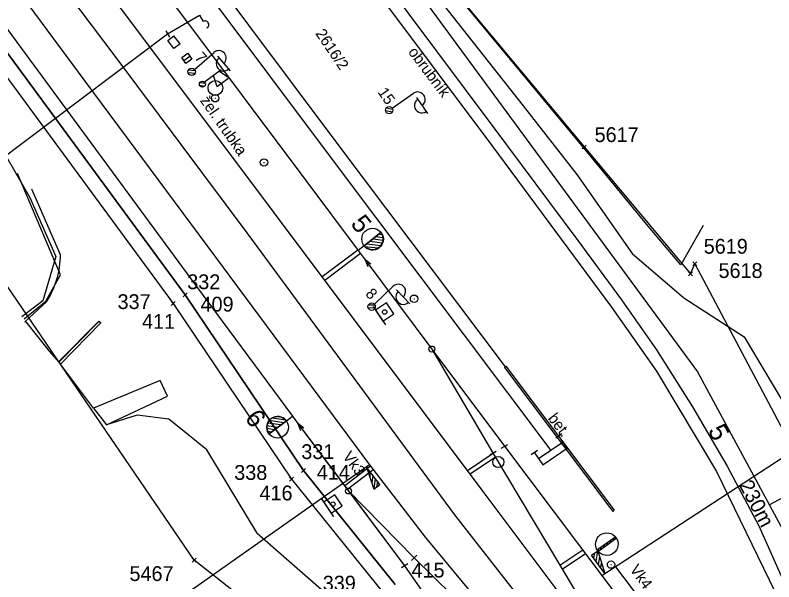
# Model space of a CAD drawing. Extents: x -804166 to -803706, y -1151030 to -1150147.
# Drawn here: x -804028.2 to -803925.7, y -1150394.5 to -1150318 of the extents above; entities that cross this region are included whole.
import ezdxf

# ---------------------------------------------------------------- set-up
doc = ezdxf.new("R2010")
doc.units = 0
for name, color, linetype in [('0381KM032-037P - Vrstva 1', 7, 'Continuous'), ('0381KM032-037P - Vrstva 13', 7, 'Continuous'), ('0381KM032-037P - Vrstva 15', 7, 'Continuous'), ('0381KM032-037P - Vrstva 16', 7, 'Continuous'), ('0381KM032-037P - Vrstva 17', 7, 'Continuous'), ('0381KM032-037P - Vrstva 2', 7, 'Continuous'), ('0381KM032-037P - Vrstva 25', 7, 'Continuous'), ('0381KM032-037P - Vrstva 27', 7, 'Continuous'), ('0381KM032-037P - Vrstva 3', 7, 'Continuous'), ('0381KM032-037P - Vrstva 33', 7, 'Continuous'), ('0381KM032-037P - Vrstva 4', 7, 'Continuous'), ('0381KM032-037P - Vrstva 41', 7, 'Continuous'), ('0381KM032-037P - Vrstva 43', 7, 'Continuous'), ('0381KM032-037P - Vrstva 48', 7, 'Continuous'), ('0381KM032-037P - Vrstva 49', 7, 'Continuous'), ('0381KM032-037P - Vrstva 50', 7, 'Continuous'), ('0381KM032-037P - Vrstva 51', 7, 'Continuous'), ('0381KM032-037P - Vrstva 57', 7, 'Continuous'), ('0381KM032-037P - Vrstva 7', 7, 'Continuous'), ('DZ_CD - CD', 7, 'Continuous'), ('DZ_CD - CD_krizek', 7, 'Continuous'), ('DZ_CD - CD_čísla', 7, 'Continuous'), ('szdc - hran DP', 7, 'Continuous'), ('szdc - szdc_cislo', 7, 'Continuous'), ('szdc - szdc_krizek', 7, 'Continuous'), ('VB - VB', 7, 'Continuous'), ('VB - VB_cislo', 7, 'Continuous'), ('VB - VB_krizek', 7, 'Continuous')]:
    doc.layers.add(name, color=color, linetype=linetype)

msp = doc.modelspace()

# ---------------------------------------------------------------- linework, layer by layer
at = {"layer": '0381KM032-037P - Vrstva 1'}
for points in [[(-804087.93, -1150205.28), (-804078.71, -1150215.28), (-804072.37, -1150222.52), (-804072.08, -1150222.85), (-804071.47, -1150223.58), (-804065.48, -1150230.82), (-804059.47, -1150238.51), (-804055.55, -1150243.68), (-804054.36, -1150245.27), (-804043.89, -1150259.22), (-804035.37, -1150270.61), (-804034.4, -1150271.93), (-804017.97, -1150293.92), (-804002.6, -1150314.46), (-803985.38, -1150337.43), (-803955.87, -1150376.72)], [(-804089.35, -1150206.44), (-804078.67, -1150220.7), (-804069.15, -1150233.38), (-804067.86, -1150235.11), (-804059.28, -1150246.53), (-804058.07, -1150248.16), (-804048.7, -1150260.65), (-804037.85, -1150275.13), (-804021.63, -1150296.76), (-804006.14, -1150317.34), (-803988.98, -1150340.29), (-803981.9, -1150349.73)], [(-804090.39, -1150214.38), (-804086.65, -1150219.55), (-804073.82, -1150237.11), (-804072.56, -1150238.83), (-804064.05, -1150250.31), (-804062.81, -1150251.97), (-804052.29, -1150266.05), (-804042.5, -1150279.11), (-804026.55, -1150300.33), (-804011.27, -1150320.63), (-803993.37, -1150344.49), (-803965.17, -1150382.07), (-803953.84, -1150397.19)], [(-804093.97, -1150217.42), (-804088.17, -1150225.67), (-804077.51, -1150240.28), (-804068.52, -1150252.21), (-804067.31, -1150253.81), (-804055.01, -1150270.12), (-804046.09, -1150281.93), (-804030.05, -1150303.21), (-804014.76, -1150323.52), (-803996.92, -1150347.35), (-803968.88, -1150385.42), (-803942.6, -1150419.03)], [(-804095.55, -1150218.38), (-804090.74, -1150227.08), (-804084.01, -1150238.21), (-804078.76, -1150245.78), (-804072.11, -1150254.85), (-804070.85, -1150256.55), (-804059.97, -1150271.29), (-804049.56, -1150285.37), (-804034.13, -1150306.22), (-804018.79, -1150326.86), (-804001.18, -1150350.63), (-803980.37, -1150378.68), (-803972.82, -1150388.42), (-803965.21, -1150397.6)], [(-804088.45, -1150239.45), (-804070.36, -1150264.07), (-804054.98, -1150285.05), (-804052.95, -1150287.79), (-804037.56, -1150308.64), (-804021.87, -1150329.91), (-804004.48, -1150353.56), (-803990.76, -1150372.09)], [(-804011.14, -1150262.39), (-804005.45, -1150273.41), (-803998.73, -1150284.85), (-803991.51, -1150295.63), (-803978.8, -1150312.77), (-803963.69, -1150332.99), (-803952.21, -1150348.36), (-803946.3, -1150356.39), (-803941.6, -1150363.14), (-803936.71, -1150370.83), (-803932.05, -1150378.84), (-803927.78, -1150386.91), (-803924.06, -1150395.18), (-803920.62, -1150403.65), (-803918.06, -1150410.86), (-803915.07, -1150420.32), (-803912.96, -1150427.25), (-803910.49, -1150435.34), (-803907.33, -1150445.05), (-803903.67, -1150454.38), (-803897.94, -1150464.6), (-803891.97, -1150476.6)], [(-803981.9, -1150349.73), (-803980.96, -1150350.97), (-803971.94, -1150363.03), (-803962.12, -1150376.15)], [(-803981.9, -1150349.73), (-803980.96, -1150350.97), (-803971.94, -1150363.03), (-803963.66, -1150377.12)], [(-803990.76, -1150372.09), (-803990.03, -1150373.08), (-803975.62, -1150392.3)], [(-803990.76, -1150372.09), (-803990.03, -1150373.08), (-803983.2, -1150382.19), (-803974.33, -1150391.21)], [(-803962.12, -1150376.15), (-803948.98, -1150393.6), (-803935.25, -1150411.89)], [(-803963.66, -1150377.12), (-803952.72, -1150395.46)], [(-803974.33, -1150391.21), (-803966.54, -1150398.86)], [(-803975.62, -1150392.3), (-803939.47, -1150444.12), (-803928.27, -1150459.42), (-803914.53, -1150477.73)]]:
    msp.add_lwpolyline(points, dxfattribs=at)
at = {"layer": '0381KM032-037P - Vrstva 13'}
for p, q in [((-804016.94, -1150359.26), (-804022.35, -1150364.74)), ((-804016.92, -1150359.32), (-804022.32, -1150364.8)), ((-804022.11, -1150365.08), (-804016.66, -1150359.51)), ((-804022.35, -1150364.74), (-804022.32, -1150364.8)), ((-804022.32, -1150364.8), (-804022.11, -1150365.08))]:
    msp.add_line(p, q, dxfattribs=at)
msp.add_lwpolyline([(-804016.66, -1150359.51), (-804016.92, -1150359.32), (-804016.94, -1150359.26), (-804016.66, -1150359.51)], dxfattribs=at)
at = {"layer": '0381KM032-037P - Vrstva 15'}
for p, q in [((-803954.37, -1150374.48), (-803955.2, -1150375.05)), ((-803954.22, -1150375.59), (-803957.52, -1150377.85)), ((-803957.67, -1150376.74), (-803958.5, -1150377.31))]:
    msp.add_line(p, q, dxfattribs=at)
msp.add_lwpolyline([(-803958.08, -1150377.03), (-803956.95, -1150378.68), (-803953.66, -1150376.41), (-803954.79, -1150374.76)], dxfattribs=at)
at = {"layer": '0381KM032-037P - Vrstva 16'}
for p, q in [((-803962.14, -1150365.5), (-803961.94, -1150365.35)), ((-803962.14, -1150365.5), (-803947.5, -1150384.94)), ((-803961.94, -1150365.35), (-803947.3, -1150384.79)), ((-803947.5, -1150384.94), (-803947.3, -1150384.79))]:
    msp.add_line(p, q, dxfattribs=at)
at = {"layer": '0381KM032-037P - Vrstva 17'}
for p, q in [((-803935.29, -1150346.34), (-803938.3, -1150351.66)), ((-804026.76, -1150359.35), (-804023.62, -1150363.33)), ((-804023.62, -1150363.33), (-804022.35, -1150364.74)), ((-804017.62, -1150371.01), (-804022.11, -1150365.08)), ((-804008.64, -1150367.29), (-804017.62, -1150371.01)), ((-804007.64, -1150369.41), (-804008.64, -1150367.29)), ((-804015.88, -1150373.24), (-804007.64, -1150369.41))]:
    msp.add_line(p, q, dxfattribs=at)
for points in [[(-803938.3, -1150351.66), (-803942.72, -1150346.43), (-803950.36, -1150337.11), (-803959.95, -1150325.57), (-803969.63, -1150313.89), (-803978.45, -1150303.11), (-803982.31, -1150298.44), (-803989.47, -1150289.34)], [(-804026.99, -1150358.95), (-804024.09, -1150356.55), (-804022.1, -1150353.01), (-804027.89, -1150339.34)], [(-804026.92, -1150359.34), (-804026.76, -1150359.35)], [(-804017.62, -1150371.01), (-804015.88, -1150373.24)]]:
    msp.add_lwpolyline(points, dxfattribs=at)
at = {"layer": '0381KM032-037P - Vrstva 2'}
for p, q in [((-803981.09, -1150349.09), (-803978.8, -1150347.27)), ((-803978.8, -1150347.27), (-803981.09, -1150349.09)), ((-803979.93, -1150348.17), (-803978.49, -1150348.33)), ((-803979.51, -1150347.84), (-803978.5, -1150347.96)), ((-803979.09, -1150347.51), (-803978.62, -1150347.56)), ((-803981.1, -1150349.09), (-803981.9, -1150349.73)), ((-803981.09, -1150349.09), (-803981.09, -1150349.09)), ((-803981.02, -1150349.17), (-803979.13, -1150349.39)), ((-803980.76, -1150348.82), (-803978.78, -1150349.06)), ((-803980.35, -1150348.49), (-803978.58, -1150348.7)), ((-803991.59, -1150372.71), (-803993.93, -1150374.46)), ((-803993.93, -1150374.46), (-803991.59, -1150372.71)), ((-803991.93, -1150372.97), (-803993.9, -1150372.68)), ((-803991.66, -1150372.63), (-803993.54, -1150372.35)), ((-803991.59, -1150372.71), (-803990.76, -1150372.09)), ((-803991.59, -1150372.71), (-803991.59, -1150372.71)), ((-803992.78, -1150373.6), (-803994.21, -1150373.39)), ((-803993.2, -1150373.92), (-803994.21, -1150373.77)), ((-803992.35, -1150373.28), (-803994.11, -1150373.03)), ((-803993.63, -1150374.24), (-803994.1, -1150374.17)), ((-803962.55, -1150376.41), (-803961.69, -1150375.9)), ((-803963.23, -1150376.87), (-803964.1, -1150377.37)), ((-803983.2, -1150382.19), (-803974.33, -1150391.21)), ((-803973.98, -1150390.86), (-803974.69, -1150391.56)), ((-803975.19, -1150392.03), (-803976.04, -1150392.56))]:
    msp.add_line(p, q, dxfattribs=at)
for points in [[(-803981.9, -1150349.73), (-803980.96, -1150350.97), (-803971.94, -1150363.03), (-803962.12, -1150376.15)], [(-803980.18, -1150351.59), (-803980.96, -1150350.97), (-803980.59, -1150351.9)], [(-803971.94, -1150363.03), (-803963.66, -1150377.12)], [(-803990.76, -1150372.09), (-803990.03, -1150373.08), (-803983.2, -1150382.19), (-803975.62, -1150392.3)], [(-803989.25, -1150373.71), (-803990.03, -1150373.08), (-803989.66, -1150374.02)]]:
    msp.add_lwpolyline(points, dxfattribs=at)
for centre, radius in [((-803979.94, -1150348.18), 1.46), ((-803971.94, -1150363.03), 0.4), ((-803992.77, -1150373.59), 1.46), ((-803983.2, -1150382.19), 0.4)]:
    msp.add_circle(centre, radius, dxfattribs=at)
for centre, start, end in [((-803979.95, -1150348.18), 218.2901, 38.251), ((-803992.76, -1150373.59), 36.7889, 216.7498)]:
    msp.add_arc(centre, 1.46, start, end, dxfattribs=at)
at = {"layer": '0381KM032-037P - Vrstva 25'}
for p, q in [((-804004.01, -1150325.29), (-804001.36, -1150322.99)), ((-804000.9, -1150323.52), (-803999.2, -1150325.49)), ((-804004.87, -1150325.72), (-804003.91, -1150325.79)), ((-804004.81, -1150325.35), (-804003.93, -1150325.41)), ((-803977.29, -1150330.5), (-803974.41, -1150328.51)), ((-803974.01, -1150329.08), (-803972.53, -1150331.22)), ((-803978.2, -1150330.83), (-803977.25, -1150331.01)), ((-803978.09, -1150330.47), (-803977.23, -1150330.63)), ((-803979.7, -1150356.96), (-803977.17, -1150354.55)), ((-803976.69, -1150355.05), (-803974.89, -1150356.93)), ((-803980.55, -1150357.43), (-803979.59, -1150357.46)), ((-803980.5, -1150357.06), (-803979.62, -1150357.08))]:
    msp.add_line(p, q, dxfattribs=at)
for centre in [(-804004.38, -1150325.62), (-804004.38, -1150325.62), (-803977.7, -1150330.78), (-803977.7, -1150330.78), (-803980.07, -1150357.31), (-803980.07, -1150357.31)]:
    msp.add_circle(centre, 0.5, dxfattribs=at)
for centre, start, end in [((-804000.71, -1150323.75), 310.9638, 130.9638), ((-804000.06, -1150324.51), 130.2612, 311.6663), ((-803973.84, -1150329.33), 304.6353, 124.6353), ((-803973.28, -1150330.16), 123.9327, 305.3379), ((-803976.48, -1150355.27), 313.6296, 133.6296), ((-803975.8, -1150356), 132.927, 314.3322)]:
    msp.add_arc(centre, 1, start, end, dxfattribs=at)
at = {"layer": '0381KM032-037P - Vrstva 27'}
for p, q in [((-803974.39, -1150356.24), (-803974.29, -1150356.24)), ((-803947.78, -1150392.13), (-803947.68, -1150392.13))]:
    msp.add_line(p, q, dxfattribs=at)
for centre in [(-803974.34, -1150356.24), (-803947.73, -1150392.13)]:
    msp.add_circle(centre, 0.5, dxfattribs=at)
at = {"layer": '0381KM032-037P - Vrstva 3'}
for p, q in [((-803994.66, -1150337.85), (-803994.56, -1150337.85)), ((-803979.88, -1150357.31), (-803978.21, -1150359.75)), ((-803978.08, -1150356.8), (-803979.54, -1150357.8)), ((-803977.08, -1150358.26), (-803978.08, -1150356.8)), ((-803979.54, -1150357.8), (-803978.54, -1150359.26)), ((-803978.54, -1150359.26), (-803977.08, -1150358.26)), ((-803948.98, -1150393.6), (-803893.86, -1150357.66)), ((-803980.37, -1150378.68), (-804019.01, -1150405.81)), ((-803980.57, -1150379.24), (-803980.6, -1150379.48)), ((-803980.25, -1150379.66), (-803980.33, -1150380.27)), ((-803979.93, -1150380.08), (-803980.06, -1150381.04)), ((-803979.61, -1150380.49), (-803979.79, -1150381.82)), ((-803979.29, -1150380.91), (-803979.4, -1150381.66)), ((-803978.98, -1150381.32), (-803978.99, -1150381.34)), ((-803986.86, -1150383.23), (-803985.21, -1150385.68)), ((-803985.06, -1150382.73), (-803986.53, -1150383.72)), ((-803984.07, -1150384.2), (-803985.06, -1150382.73)), ((-803986.53, -1150383.72), (-803985.54, -1150385.19)), ((-803985.54, -1150385.19), (-803984.07, -1150384.2)), ((-803948.26, -1150389.47), (-803948.21, -1150389.18)), ((-803947.82, -1150389.15), (-803947.78, -1150388.87)), ((-803947.39, -1150388.84), (-803947.34, -1150388.55)), ((-803947.1, -1150388.64), (-803947.1, -1150388.6)), ((-803949.74, -1150391.69), (-803949.51, -1150390.29)), ((-803949.14, -1150390.1), (-803949.08, -1150389.8)), ((-803948.7, -1150389.78), (-803948.65, -1150389.49)), ((-803950.05, -1150391.26), (-803949.94, -1150390.55)), ((-803949.43, -1150392.13), (-803949.25, -1150391.1)), ((-803949.12, -1150392.56), (-803949, -1150391.92)), ((-803948.8, -1150392.99), (-803948.75, -1150392.72))]:
    msp.add_line(p, q, dxfattribs=at)
for points in [[(-803980.77, -1150378.99), (-803979.76, -1150381.93), (-803978.97, -1150381.33), (-803980.77, -1150378.99)], [(-803947.08, -1150388.62), (-803947.2, -1150388.45), (-803949.5, -1150390.11), (-803949.38, -1150390.27), (-803947.08, -1150388.62)], [(-803948.58, -1150393.31), (-803950.35, -1150390.85), (-803949.52, -1150390.25), (-803948.58, -1150393.31)]]:
    msp.add_lwpolyline(points, dxfattribs=at)
msp.add_lwpolyline([(-803947.08, -1150388.62), (-803947.2, -1150388.45), (-803949.5, -1150390.11), (-803949.38, -1150390.27)], close=True, dxfattribs=at)
for centre, radius in [((-803994.61, -1150337.85), 0.5), ((-803978.31, -1150358.03), 0.296), ((-803985.3, -1150383.96), 0.296)]:
    msp.add_circle(centre, radius, dxfattribs=at)
msp.add_ellipse((-803948.29, -1150389.36), major_axis=(-1.23, -0.89), ratio=0.999996, dxfattribs=at)
at = {"layer": '0381KM032-037P - Vrstva 33'}
for p, q in [((-804000.39, -1150325.35), (-804002.63, -1150327.02)), ((-804000.63, -1150325.53), (-803999.33, -1150326.43)), ((-804000.93, -1150327.62), (-804001.43, -1150326.12)), ((-803999.33, -1150326.43), (-804000.93, -1150327.62)), ((-804003.3, -1150327.43), (-804002.63, -1150327.53)), ((-804003.25, -1150327.03), (-804002.56, -1150327.14))]:
    msp.add_line(p, q, dxfattribs=at)
msp.add_circle((-804002.93, -1150327.28), 0.401, dxfattribs=at)
msp.add_circle((-804002.93, -1150327.28), 0.401, dxfattribs=at)
at = {"layer": '0381KM032-037P - Vrstva 4'}
for points in [[(-804015.09, -1150257.7), (-804005.61, -1150276.65), (-803997.81, -1150289.61), (-803985.99, -1150305.97), (-803963.83, -1150335.54), (-803947.69, -1150357.39), (-803941.6, -1150366.02), (-803933.49, -1150379.54), (-803925.57, -1150395.83), (-803919.57, -1150411.36), (-803915.11, -1150425.7)], [(-804033.34, -1150270.47), (-804023.51, -1150283.74), (-804006.75, -1150306.05), (-804002.75, -1150311.23), (-803984.52, -1150335.59), (-803962.04, -1150365.45)]]:
    msp.add_lwpolyline(points, dxfattribs=at)
at = {"layer": '0381KM032-037P - Vrstva 41'}
for p, q in [((-804007.63, -1150320.5), (-804003.32, -1150317.97)), ((-804003.32, -1150317.97), (-804002.82, -1150318.83)), ((-804063.79, -1150362.63), (-804007.63, -1150320.5)), ((-804007.89, -1150320.07), (-804007.38, -1150320.93))]:
    msp.add_line(p, q, dxfattribs=at)
msp.add_arc((-804002.56, -1150319.25), 0.5, 299.3257, 121.6172, dxfattribs=at)
at = {"layer": '0381KM032-037P - Vrstva 43'}
msp.add_line((-804005.93, -1150321.83), (-804006.77, -1150320.75), dxfattribs=at)
for points in [[(-804005.93, -1150321.83), (-804006.79, -1150322.47), (-804007.61, -1150321.38), (-804006.77, -1150320.75)], [(-804005.45, -1150324.07), (-804005.73, -1150323.66), (-804004.91, -1150323.09), (-804004.34, -1150323.91), (-804005.16, -1150324.48), (-804005.45, -1150324.07), (-804004.63, -1150323.5)]]:
    msp.add_lwpolyline(points, dxfattribs=at)
msp.add_circle((-804001.17, -1150327.79), 1, dxfattribs=at)
at = {"layer": '0381KM032-037P - Vrstva 48'}
msp.add_line((-803918.27, -1150379.71), (-803926.34, -1150384.07), dxfattribs=at)
at = {"layer": '0381KM032-037P - Vrstva 49'}
for p, q in [((-804022.74, -1150350.54), (-804024.47, -1150356.54)), ((-804024.47, -1150356.54), (-804027.3, -1150358.69)), ((-803929.73, -1150361.39), (-803920.94, -1150376.21))]:
    msp.add_line(p, q, dxfattribs=at)
for points in [[(-804010.87, -1150255.86), (-804001.61, -1150274.67), (-803994.7, -1150286.68), (-803981.46, -1150304.36), (-803936.05, -1150366.09), (-803921.77, -1150392.54), (-803912.22, -1150419.28), (-803908.81, -1150430.91)], [(-804067.58, -1150273.2), (-804053.47, -1150291.61), (-804044.04, -1150305.1), (-804036.58, -1150319.92), (-804030.41, -1150335.37), (-804026.23, -1150342.57), (-804022.74, -1150350.54)], [(-803989.47, -1150289.34), (-803982.88, -1150300.61), (-803979.03, -1150305.25), (-803971.78, -1150314.79), (-803959.62, -1150330.2), (-803952.37, -1150339.47), (-803944.88, -1150350.15), (-803937.92, -1150356.12), (-803929.73, -1150361.39)], [(-803995.51, -1150387.87), (-804002.35, -1150376.64), (-804007.46, -1150372.51), (-804011.72, -1150371.94), (-804015.88, -1150373.24)], [(-803995.51, -1150387.87), (-803978.95, -1150402.37), (-803967.97, -1150412.01), (-803952.57, -1150434.32)]]:
    msp.add_lwpolyline(points, dxfattribs=at)
at = {"layer": '0381KM032-037P - Vrstva 50'}
msp.add_line((-804001.26, -1150329.18), (-804001.16, -1150329.18), dxfattribs=at)
msp.add_circle((-804001.21, -1150329.18), 0.5, dxfattribs=at)
at = {"layer": '0381KM032-037P - Vrstva 51'}
for p, q in [((-804022.1, -1150350.3), (-804025.97, -1150341.45)), ((-804026.92, -1150359.34), (-804023.98, -1150356.66)), ((-803947.12, -1150392.44), (-803936.56, -1150406.26))]:
    msp.add_line(p, q, dxfattribs=at)
msp.add_lwpolyline([(-804015.09, -1150257.7), (-804005.61, -1150276.65), (-803997.81, -1150289.61), (-803985.99, -1150305.97), (-803963.83, -1150335.54), (-803947.69, -1150357.39), (-803941.6, -1150366.02), (-803933.49, -1150379.54), (-803925.57, -1150395.83), (-803919.57, -1150411.36), (-803915.11, -1150425.7)], dxfattribs=at)
msp.add_ellipse((-804033.55, -1150350.88), major_axis=(7.51, 9.2), ratio=0.940819, start_param=4.845934, end_param=5.41758, dxfattribs=at)
at = {"layer": '0381KM032-037P - Vrstva 7'}
for p, q in [((-803981.94, -1150349.67), (-803986.77, -1150353.29)), ((-803981.58, -1150350.15), (-803986.41, -1150353.77)), ((-803963.66, -1150377.12), (-803967.14, -1150379.45)), ((-803963.35, -1150377.64), (-803966.78, -1150379.93)), ((-803980.24, -1150378.86), (-803983.71, -1150381.51)), ((-803979.87, -1150379.33), (-803983.35, -1150381.99)), ((-803951.56, -1150390.2), (-803954.63, -1150392.26)), ((-803951.2, -1150390.68), (-803954.32, -1150392.78))]:
    msp.add_line(p, q, dxfattribs=at)
msp.add_circle((-803962.96, -1150378.29), 0.75, dxfattribs=at)
at = {"layer": 'DZ_CD - CD'}
for p, q in [((-804042.88, -1150308), (-804006.89, -1150356.88)), ((-804005.25, -1150355.72), (-804040.67, -1150307.63)), ((-803989.28, -1150379.42), (-804005.25, -1150355.72)), ((-804006.89, -1150356.88), (-803990.89, -1150380.61)), ((-803976.88, -1150394.8), (-803989.28, -1150379.42)), ((-803990.89, -1150380.61), (-803978.48, -1150396))]:
    msp.add_line(p, q, dxfattribs=at)
at = {"layer": 'DZ_CD - CD_krizek'}
for p, q in [((-804004.99, -1150355.99), (-804005.52, -1150355.46)), ((-804005.52, -1150355.99), (-804004.99, -1150355.46)), ((-804006.62, -1150357.14), (-804007.15, -1150356.61)), ((-804007.15, -1150357.14), (-804006.62, -1150356.61)), ((-803989.01, -1150379.68), (-803989.54, -1150379.15)), ((-803989.54, -1150379.68), (-803989.01, -1150379.15)), ((-803990.62, -1150380.87), (-803991.16, -1150380.34)), ((-803991.16, -1150380.87), (-803990.62, -1150380.34))]:
    msp.add_line(p, q, dxfattribs=at)
at = {"layer": 'szdc - hran DP'}
for p, q in [((-803972.77, -1150310.06), (-803951.37, -1150335.75)), ((-803951.37, -1150335.75), (-803936.98, -1150352.88)), ((-804004.05, -1150391.51), (-804033.86, -1150347.88)), ((-803936.98, -1150352.88), (-803936.41, -1150351.52)), ((-803936.41, -1150351.52), (-803914.94, -1150392.05)), ((-803965.92, -1150421.41), (-804004.05, -1150391.51))]:
    msp.add_line(p, q, dxfattribs=at)
at = {"layer": 'szdc - szdc_krizek'}
for p, q in [((-803951.1, -1150336.02), (-803951.64, -1150335.49)), ((-803951.64, -1150336.02), (-803951.1, -1150335.49)), ((-803936.15, -1150351.78), (-803936.68, -1150351.26)), ((-803936.68, -1150351.78), (-803936.15, -1150351.26)), ((-803936.71, -1150353.15), (-803937.25, -1150352.61)), ((-803937.25, -1150353.15), (-803936.71, -1150352.61)), ((-804003.79, -1150391.78), (-804004.32, -1150391.25)), ((-804004.32, -1150391.78), (-804003.79, -1150391.25))]:
    msp.add_line(p, q, dxfattribs=at)
at = {"layer": 'VB - VB'}
for p, q in [((-804078.87, -1150259.13), (-804006.89, -1150356.88)), ((-804076.08, -1150259.54), (-804005.25, -1150355.72))]:
    msp.add_line(p, q, dxfattribs=at)
for points in [[(-804005.25, -1150355.72), (-803989.28, -1150379.42), (-803976.88, -1150394.8)], [(-804006.89, -1150356.88), (-803990.89, -1150380.61), (-803978.48, -1150396)]]:
    msp.add_lwpolyline(points, dxfattribs=at)
at = {"layer": 'VB - VB_krizek'}
for p, q in [((-804004.99, -1150355.99), (-804005.52, -1150355.46)), ((-804005.52, -1150355.99), (-804004.99, -1150355.46)), ((-804006.62, -1150357.14), (-804007.15, -1150356.61)), ((-804007.15, -1150357.14), (-804006.62, -1150356.61)), ((-803989.01, -1150379.68), (-803989.54, -1150379.15)), ((-803989.54, -1150379.68), (-803989.01, -1150379.15)), ((-803990.62, -1150380.87), (-803991.16, -1150380.34)), ((-803991.16, -1150380.87), (-803990.62, -1150380.34))]:
    msp.add_line(p, q, dxfattribs=at)

# ---------------------------------------------------------------- texts
at = {"layer": '0381KM032-037P - Vrstva 1'}
for s, height, p in [('5', 2.5, (-803934.7, -1150374.01)), ('230m', 2, (-803930.5, -1150381.37))]:
    msp.add_text(s, height=height, rotation=297.8842, dxfattribs=at).set_placement(p)
at = {"layer": '0381KM032-037P - Vrstva 16'}
msp.add_text('bet.', height=1.5, rotation=306.9853, dxfattribs=at).set_placement((-803956.33, -1150372.39))
at = {"layer": '0381KM032-037P - Vrstva 2'}
for s, rotation, p in [('5', 308.2705, (-803983.01, -1150346.15)), ('6', 306.7693, (-803997.29, -1150372.37))]:
    msp.add_text(s, height=2.5, rotation=rotation, dxfattribs=at).set_placement(p)
at = {"layer": '0381KM032-037P - Vrstva 25'}
for s, rotation, p in [('7', 310.9638, (-804004.06, -1150323.75)), ('15', 304.6353, (-803979.31, -1150328.36)), ('8', 313.6296, (-803981, -1150355.67))]:
    msp.add_text(s, height=1.5, rotation=rotation, dxfattribs=at).set_placement(p)
at = {"layer": '0381KM032-037P - Vrstva 3'}
for s, rotation, p in [('Vk3', 306.528, (-803984.06, -1150377.53)), ('Vk4', 305.7164, (-803945.27, -1150392.78))]:
    msp.add_text(s, height=1.5, rotation=rotation, dxfattribs=at).set_placement(p)
at = {"layer": '0381KM032-037P - Vrstva 50'}
msp.add_text('žel. trubka', height=1.5, rotation=305, dxfattribs=at).set_placement((-804003.31, -1150329.5))
at = {"layer": '0381KM032-037P - Vrstva 51'}
msp.add_text('obrubník', height=1.5, rotation=306.842, dxfattribs=at).set_placement((-803975.21, -1150322.95))
at = {"layer": '0381KM032-037P - Vrstva 57'}
msp.add_text('2616/2', height=1.5, rotation=303.9651, dxfattribs=at).set_placement((-803987.73, -1150320.43))
at = {"layer": 'DZ_CD - CD_čísla'}
for s, p in [('332', (-804004.98, -1150354.95)), ('337', (-804014.39, -1150357.63)), ('331', (-803989.57, -1150377.88)), ('338', (-803998.63, -1150380.69)), ('339', (-803986.67, -1150395.63))]:
    msp.add_text(s, height=2, dxfattribs=at).set_placement(p)
at = {"layer": 'szdc - szdc_cislo'}
for s, p in [('5617', (-803949.95, -1150335.09)), ('5619', (-803935.21, -1150350.16)), ('5618', (-803933.21, -1150353.44)), ('5467', (-804012.78, -1150394.34))]:
    msp.add_text(s, height=2, dxfattribs=at).set_placement(p)
at = {"layer": 'VB - VB_cislo'}
for s, p in [('409', (-804003.18, -1150357.97)), ('411', (-804011.08, -1150360.3)), ('414', (-803987.48, -1150380.67)), ('416', (-803995.22, -1150383.46)), ('415', (-803974.68, -1150393.87))]:
    msp.add_text(s, height=2, dxfattribs=at).set_placement(p)

doc.saveas('drawing.dxf')
